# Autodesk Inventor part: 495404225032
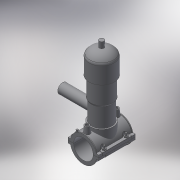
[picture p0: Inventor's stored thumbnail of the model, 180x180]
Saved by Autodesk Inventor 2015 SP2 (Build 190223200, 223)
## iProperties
Created: 2017-07
Part Number: 495404225032
Material: Generic
Description: PLASSON TAPPING VALVE 225-32
Document SubType Name: Modeling
Designer: KIM
Density: 1 g/cm^3
Appearance: Default
Author: KIM
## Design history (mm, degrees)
derived "495404-4954S4.ipt"
feature "Solid1::495404-4954S4.ipt"
feature "Solid2::495404-4954S4.ipt"
tag "TaggingFeature1"
body "Solid1"
body "Solid2"
other parameters: "d0" = 225, "d2" = 295.1, "d3" = 56.25, "d4" = 176, "d5" = 0, "d6" = 0.1, "d8" = 0, "d19" = 6, "d20" = 6, "d21" = 105.6, "d23" = 0, "d24" = 52.8, "d26" = 0, "d27" = 3, "d28" = 3, "d29" = 3, "d30" = 75, "d31" = 6, "d32" = 0, "d33" = 0, "d34" = 0.6, "d40" = 136.89, "d47" = 177.625, "d70" = 15, "d72" = 0, "d73" = 6, "d75" = 5, "d76" = 0, "d77" = 11.25, "d78" = 142.5, "d79" = 15, "d80" = 70.4, "d82" = 5 deg, "d84" = 4, "d85" = 14, "d86" = 0, "d87" = 3, "d88" = 0, "d89" = 1, "d90" = 1, "d91" = 140.8, "d92" = 0, "d93" = 0.5, "d94" = 118.42105, "d96" = 271.1475, "d97" = 3.52, "d98" = 0, "d120" = 140 deg, "d121" = 24.228, "d122" = 20 deg, "d123" = 526.5, "d124" = 157.95, "d126" = 0, "d143" = 231.75, "d145" = 29.42308, "d149" = 3.375, "d150" = 32.36538, "d153" = 176, "d154" = 0, "d156" = 131.625, "d157" = 160 deg, "d159" = 7.65, "d161" = 3.375, "d162" = 105.6, "d163" = 0, "d164" = 112.5, "d167" = 22.5, "d168" = 128.41463, "d170" = 3.375, "d172" = 0, "d173" = 1, "d175" = 112.5, "d176" = 20 deg, "d177" = 15.75, "d178" = 38.25, "d180" = 0, "d183" = 15.3, "d184" = 12.6, "d185" = 57.2, "d186" = 57.2, "d187" = 131.625, "d188" = 11.475, "d189" = 15.75, "d190" = 0, "d191" = 197.4375, "d193" = 7.65, "d194" = 4.4, "d195" = 90 deg, "d197" = 0, "d199" = 0, "d205" = 14.64, "d206" = 81.33333, "d207" = 244, "d208" = 224.48, "d209" = 207.4, "d210" = 200.08, "d211" = 146.4, "d212" = 85.4, "d213" = 65.88, "d214" = 73.2, "d216" = 21.96, "d217" = 70.76, "d218" = 80.52, "d220" = 225, "d222" = 0, "d223" = 263.25, "d224" = 126, "d225" = 46, "d226" = 32, "d229" = 126, "d230" = 0, "d_" = 225, "B_" = 227, "H_" = 126, "L_" = 176, "d_t" = 6, "d_1" = 32, "H_1" = 46, "H_2" = 244, "d148" = 3.375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
